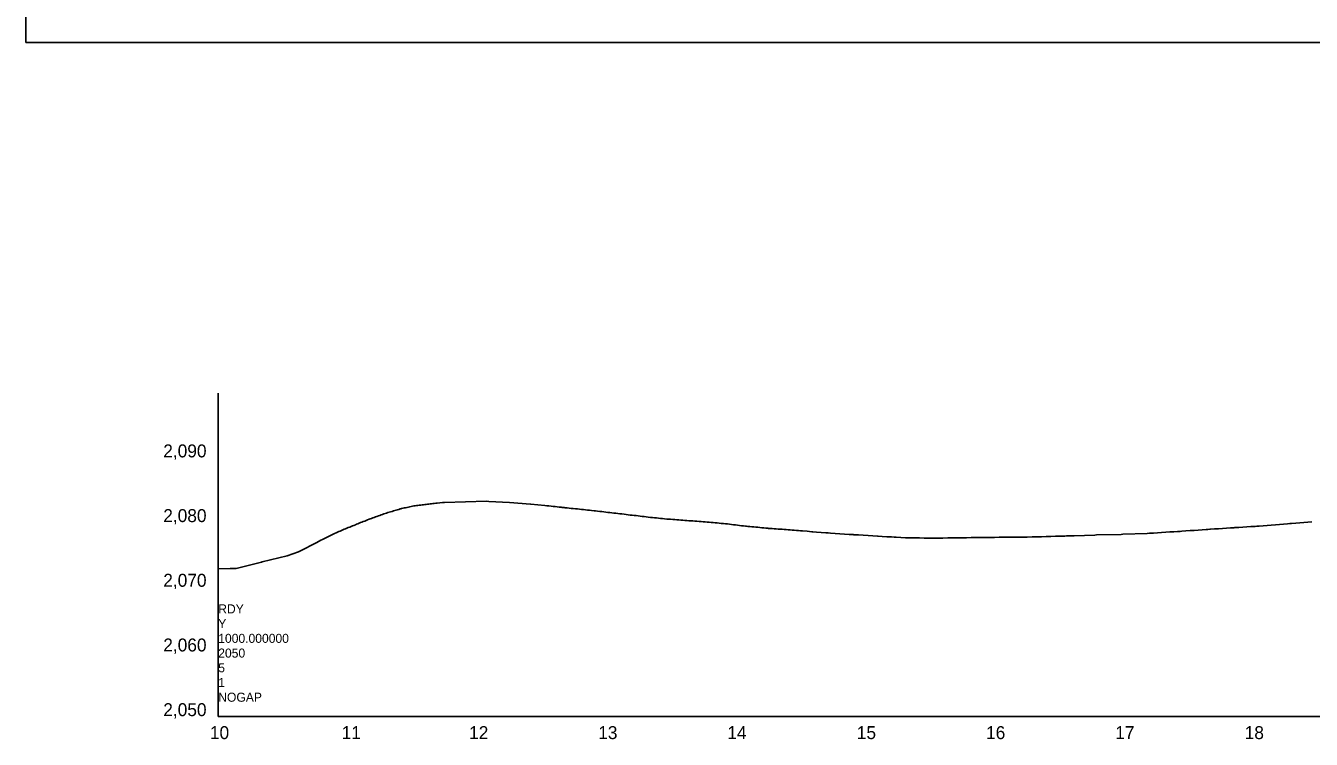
# Model space of a CAD drawing. Extents: x 757145 to 758829, y 592169 to 594973.
# Drawn here: x 757145 to 758139, y 592169 to 592721 of the extents above; entities that cross this region are included whole.
import ezdxf

# ---------------------------------------------------------------- set-up
doc = ezdxf.new("R2010")
doc.units = 0
for name, color, linetype in [('Exist CMT EOP', 7, 'Continuous'), ('Old_Level_63', 7, 'Continuous'), ('Prop CMT DNC', 7, 'Continuous'), ('Scratch_Level_4', 7, 'Continuous'), ('Sheet Cutting Line CELL', 7, 'Continuous'), ('Sheet Plot Border Outside CELL', 7, 'Continuous')]:
    doc.layers.add(name, color=color, linetype=linetype)

msp = doc.modelspace()

# ---------------------------------------------------------------- linework, layer by layer
at = {"layer": 'Exist CMT EOP'}
for points in [[(757294.27, 592300.93), (757303.48, 592301.14), (757307.32, 592301.24), (757308.13, 592301.29), (757327.63, 592306.18), (757328.36, 592306.36), (757347.61, 592311.09), (757356.42, 592314.2), (757357.47, 592314.67), (757370.55, 592321.43), (757373.72, 592323.05), (757374.78, 592323.59), (757375.98, 592324.2), (757376.89, 592324.67), (757377.95, 592325.21), (757379, 592325.75), (757380.06, 592326.29), (757381.12, 592326.82), (757382.17, 592327.36), (757383.23, 592327.9), (757384.28, 592328.42), (757385.34, 592328.87), (757386.39, 592329.32), (757387.45, 592329.76), (757388.51, 592330.21), (757389.56, 592330.66), (757390.64, 592331.11), (757391.67, 592331.54), (757392.73, 592331.98), (757393.79, 592332.41), (757394.84, 592332.85), (757395.9, 592333.28), (757396.95, 592333.72), (757398.01, 592334.15), (757399.07, 592334.58), (757400.36, 592335.11), (757401.22, 592335.46), (757402.23, 592335.87), (757403.29, 592336.29), (757404.34, 592336.71), (757405.4, 592337.12), (757406.46, 592337.54), (757407.51, 592337.95), (757408.57, 592338.37), (757409.62, 592338.78), (757410.97, 592339.31), (757411.74, 592339.59), (757412.79, 592339.99), (757413.85, 592340.38), (757414.9, 592340.77), (757415.96, 592341.16), (757417.01, 592341.55), (757418.07, 592341.94), (757419.13, 592342.32), (757420.18, 592342.69), (757421.24, 592343.05), (757422.29, 592343.4), (757423.35, 592343.76), (757424.41, 592344.11), (757425.46, 592344.46), (757426.52, 592344.8), (757427.57, 592345.11), (757428.63, 592345.42), (757429.69, 592345.73), (757430.74, 592346.03), (757431.8, 592346.34), (757432.85, 592346.64), (757433.91, 592346.94), (757434.96, 592347.24), (757435.38, 592347.36), (757436.02, 592347.55), (757437.08, 592347.78), (757438.13, 592348.01), (757439.19, 592348.24), (757440.24, 592348.47), (757441.3, 592348.69), (757442.36, 592348.92), (757443.41, 592349.14), (757444.47, 592349.37), (757445.52, 592349.6), (757446.58, 592349.72), (757447.63, 592349.86), (757448.69, 592350), (757449.75, 592350.14), (757450.8, 592350.28), (757451.86, 592350.41), (757452.91, 592350.55), (757453.97, 592350.68), (757455.03, 592350.81), (757456.08, 592350.94), (757457.14, 592351.07), (757458.19, 592351.2), (757459.25, 592351.33), (757460.3, 592351.45), (757461.36, 592351.58), (757462.42, 592351.7), (757463.47, 592351.83), (757467.75, 592352.32), (757468.12, 592352.33), (757469.35, 592352.37), (757501.71, 592353.29)], [(757501.71, 592353.29), (757503.53, 592353.04), (757519.42, 592352.32), (757535.7, 592351), (757536.01, 592350.96), (757541.43, 592350.46), (757546.88, 592349.9), (757548.45, 592349.73), (757550.01, 592349.57), (757551.58, 592349.41), (757553.15, 592349.24), (757554.72, 592349.08), (757556.28, 592348.92), (757557.85, 592348.75), (757559.42, 592348.59), (757560.27, 592348.5), (757560.99, 592348.42), (757561.8, 592348.33), (757562.55, 592348.25), (757564.12, 592348.09), (757565.69, 592347.92), (757567.26, 592347.75), (757568.82, 592347.58), (757570.39, 592347.41), (757571.96, 592347.24), (757573.53, 592347.07), (757575.09, 592346.9), (757576.66, 592346.73), (757578.23, 592346.56), (757579.8, 592346.39), (757581.36, 592346.22), (757582.93, 592346.05), (757584.85, 592345.84), (757586.07, 592345.7), (757587.63, 592345.53), (757589.2, 592345.35), (757590.77, 592345.18), (757592.34, 592345), (757593.91, 592344.83), (757595.47, 592344.64), (757595.84, 592344.59), (757597.04, 592344.47), (757598.61, 592344.3), (757600.18, 592344.13), (757601.74, 592343.95), (757603.31, 592343.77), (757604.88, 592343.58), (757606.45, 592343.39), (757608.01, 592343.2), (757609.58, 592343), (757611.15, 592342.8), (757612.72, 592342.59), (757614.28, 592342.43), (757615.85, 592342.26), (757617.42, 592342.09), (757618.99, 592341.92), (757620.55, 592341.74), (757622.12, 592341.56), (757623.69, 592341.37), (757625.26, 592341.18), (757626.82, 592340.98), (757628.39, 592340.78), (757628.76, 592340.73), (757629.3, 592340.66), (757629.96, 592340.6), (757631.53, 592340.46), (757633.1, 592340.31), (757634.66, 592340.15), (757636.23, 592339.99), (757637.8, 592339.83), (757639.37, 592339.66), (757641.14, 592339.47), (757642.16, 592339.42), (757642.5, 592339.4), (757644.07, 592339.3), (757645.64, 592339.19), (757647.2, 592339.08), (757648.77, 592338.97), (757650.34, 592338.85), (757651.91, 592338.73), (757653.47, 592338.6), (757655.04, 592338.47), (757656.61, 592338.34), (757658.18, 592338.2), (757658.78, 592338.14), (757659.95, 592338.09), (757661.31, 592338), (757662.88, 592337.9), (757664.45, 592337.79), (757666.01, 592337.67), (757667.58, 592337.55), (757669.15, 592337.43), (757670.72, 592337.3), (757672.28, 592337.17), (757673.85, 592337.04), (757675.42, 592336.9), (757676.41, 592336.81), (757676.99, 592336.75), (757678.56, 592336.6), (757680.12, 592336.44), (757681.69, 592336.28)], [(757681.69, 592336.28), (757683.26, 592336.11), (757684.83, 592335.94), (757686.46, 592335.76), (757687.96, 592335.65), (757689.53, 592335.47), (757691.1, 592335.29), (757692.66, 592335.11), (757694.23, 592334.92), (757695.8, 592334.74), (757697.37, 592334.54), (757698.93, 592334.35), (757700.5, 592334.15), (757702.07, 592333.95), (757702.76, 592333.86), (757703.64, 592333.79), (757705.2, 592333.65), (757706.77, 592333.51), (757708.34, 592333.37), (757709.91, 592333.22), (757711.47, 592333.07), (757713.04, 592332.92), (757714.61, 592332.76), (757716.18, 592332.6), (757717.75, 592332.44), (757718.65, 592332.35), (757719.31, 592332.3), (757719.79, 592332.27), (757720.88, 592332.2), (757722.45, 592332.09), (757724.02, 592331.99), (757725.58, 592331.88), (757727.15, 592331.77), (757728.72, 592331.65), (757730.29, 592331.54), (757731.85, 592331.42), (757733.42, 592331.3), (757734.99, 592331.17), (757736.56, 592331.04), (757738.12, 592330.92), (757739.69, 592330.78), (757741.26, 592330.65), (757741.84, 592330.6), (757742.29, 592330.56), (757742.83, 592330.52), (757744.39, 592330.4), (757745.96, 592330.27), (757749.58, 592329.98), (757753.25, 592329.68), (757753.96, 592329.62), (757756.83, 592329.41), (757760.45, 592329.15), (757764.08, 592328.88), (757764.67, 592328.83), (757765.89, 592328.76), (757767.7, 592328.64), (757771.32, 592328.39), (757774.94, 592328.14), (757778.57, 592327.88), (757782.19, 592327.63), (757784.38, 592327.47), (757785.21, 592327.43), (757785.81, 592327.39), (757789.43, 592327.15), (757793.06, 592326.9), (757796.68, 592326.65), (757800.3, 592326.4), (757804.1, 592326.14), (757804.51, 592326.13), (757807.55, 592325.97), (757811.17, 592325.79), (757814.79, 592325.61), (757816.8, 592325.5), (757818.42, 592325.42), (757822.04, 592325.22), (757825.66, 592325.02), (757826.3, 592324.99), (757829.29, 592324.95), (757832.91, 592324.9), (757836.53, 592324.85), (757840.15, 592324.81), (757843.78, 592324.76), (757847.4, 592324.71), (757848.07, 592324.7), (757848.62, 592324.7), (757851.02, 592324.73), (757854.64, 592324.78), (757858.27, 592324.83), (757861.89, 592324.88), (757865.51, 592324.93), (757869.32, 592324.99), (757870.13, 592324.99), (757872.76, 592325.03), (757876.38, 592325.08), (757880, 592325.14), (757883.63, 592325.19), (757887.25, 592325.25), (757890.57, 592325.29), (757890.87, 592325.3), (757891.52, 592325.3), (757894.49, 592325.33)], [(757894.49, 592325.33), (757898.12, 592325.36), (757901.74, 592325.39), (757905.36, 592325.42), (757908.99, 592325.45), (757909.34, 592325.45), (757910.48, 592325.47), (757912.61, 592325.49), (757916.23, 592325.54), (757919.85, 592325.59), (757923.48, 592325.64), (757927.1, 592325.69), (757928.14, 592325.71), (757929.53, 592325.75), (757930.72, 592325.79), (757934.35, 592325.89), (757937.97, 592326), (757941.59, 592326.11), (757945.21, 592326.22), (757948.84, 592326.33), (757950.15, 592326.37), (757951.51, 592326.42), (757952.46, 592326.46), (757956.08, 592326.58), (757972.18, 592327.13), (757973.31, 592327.18), (757992.39, 592327.64), (757993.63, 592327.71), (758012.58, 592328.37), (758014.36, 592328.47), (758017.41, 592328.67), (758020.55, 592328.87), (758023.69, 592329.07), (758026.83, 592329.27), (758029.97, 592329.47), (758033.11, 592329.66), (758035.9, 592329.84), (758036.26, 592329.86), (758038.1, 592329.97), (758039.4, 592330.06), (758042.54, 592330.29), (758045.68, 592330.51), (758048.82, 592330.73), (758051.96, 592330.95), (758055.1, 592331.17), (758058.24, 592331.39), (758059.3, 592331.46), (758061.03, 592331.57), (758061.38, 592331.59), (758064.52, 592331.79), (758067.66, 592332), (758070.8, 592332.2), (758073.94, 592332.41), (758077.08, 592332.61), (758078.32, 592332.69), (758079.55, 592332.76), (758080.22, 592332.81), (758083.37, 592333.01), (758086.51, 592333.22), (758089.65, 592333.42), (758092.79, 592333.63), (758095.93, 592333.83), (758097.28, 592333.92), (758098.01, 592333.98), (758099.07, 592334.07), (758102.21, 592334.32), (758105.35, 592334.57), (758108.49, 592334.82), (758111.63, 592335.08), (758114.77, 592335.33), (758117.91, 592335.58), (758121.05, 592335.83), (758122.88, 592335.97), (758124.19, 592336.07), (758127.34, 592336.3), (758130.48, 592336.54), (758133.62, 592336.77), (758136.76, 592337.01), (758139.9, 592337.24)]]:
    msp.add_lwpolyline(points, dxfattribs=at)
at = {"layer": 'Scratch_Level_4'}
for q in [(757294.27, 592436.88), (758723.95, 592186.88), (757294.27, 592186.88)]:
    msp.add_line((757294.27, 592186.88), q, dxfattribs=at)
at = {"layer": 'Sheet Cutting Line CELL'}
for p, q in [((757145.42, 593802.83), (757145.42, 592707.83)), ((757145.42, 592707.83), (758828.92, 592707.83))]:
    msp.add_line(p, q, dxfattribs=at)
at = {"layer": 'Sheet Plot Border Outside CELL'}
msp.add_lwpolyline([(757145.42, 592707.83), (758828.92, 592707.83), (758828.92, 593802.83), (757145.42, 593802.83)], close=True, dxfattribs=at)

# ---------------------------------------------------------------- texts
at = {"layer": 'Old_Level_63'}
for s, p in [('2,090', (757251.77, 592387.13)), ('2,080', (757251.77, 592337.13)), ('2,070', (757251.77, 592287.13)), ('2,060', (757251.77, 592237.13)), ('2,050', (757251.77, 592187.13))]:
    msp.add_text(s, height=10, dxfattribs=at).set_placement(p)
at = {"layer": 'Prop CMT DNC'}
for s, p in [('10', (757287.85, 592169.38)), ('11', (757389.69, 592169.38)), ('12', (757488.24, 592169.38)), ('13', (757588.07, 592169.38)), ('14', (757687.92, 592169.38)), ('15', (757788.01, 592169.38)), ('16', (757887.95, 592169.38)), ('17', (757987.81, 592169.38)), ('18', (758087.93, 592169.38))]:
    msp.add_text(s, height=10, dxfattribs=at).set_placement(p)
at = {"layer": 'Scratch_Level_4'}
for s, p in [('RDY', (757294.27, 592266.5)), ('Y', (757294.27, 592255.13)), ('1000.000000', (757294.27, 592243.75)), ('2050', (757294.27, 592232.38)), ('5', (757294.27, 592221)), ('1', (757294.27, 592209.63)), ('NOGAP', (757294.27, 592198.25))]:
    msp.add_text(s, height=7, dxfattribs=at).set_placement(p)

doc.saveas('drawing.dxf')
